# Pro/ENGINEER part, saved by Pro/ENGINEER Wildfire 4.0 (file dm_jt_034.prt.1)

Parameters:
  METRIC = "NO"

Other parameters: PITCH, DRILL_DIAMETER, THREAD_DIAMETER, THREADS_PER_INCH, DRILL_POINT_ANGLE, DRILL_DEPTH, THREAD_DEPTH, THREAD_LENGTH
